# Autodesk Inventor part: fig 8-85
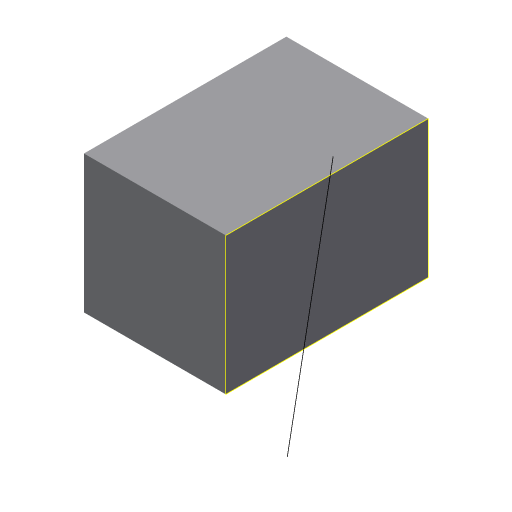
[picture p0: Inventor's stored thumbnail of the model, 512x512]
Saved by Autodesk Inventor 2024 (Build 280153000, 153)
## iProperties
Created: 2009-04
Part Number: fig 8-85
Document SubType Name: Modeling
Designer: Sham
Density: 1 g/cm^3
Material: Generic
Appearance: Default
Author: Sham
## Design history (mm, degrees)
sketch "Sketch5"
  geometry: L1 (14, -13.6)-(0, -13.6); L2 (0, -13.6)-(0, 0); L3 (0, 0)-(14, 0); L4 (14, 0)-(14, -13.6)
  constraints: 8 end point
extrude "Extrusion2" new body sketch "Sketch5" distance "d3" = 20; taper "d4" = 0 deg
sketch "Sketch7"
  geometry: L1 (13.6, 20)-(0, 20) reference; L2 (0, 0)-(0, 20) reference; L3 (13.6, 0)-(0, 0) reference; L4 (13.6, 0)-(13.6, 20) reference; L5 (-1.442, 10.604)-(21.986, 6.075)
  constraints: 2 end point
body "Solid2"
